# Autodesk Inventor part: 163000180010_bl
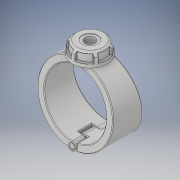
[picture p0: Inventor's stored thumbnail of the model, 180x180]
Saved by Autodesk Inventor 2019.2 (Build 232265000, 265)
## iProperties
Created: 2022-02
Part Number: 163000180010_bl
Material: Generic
Description: Plassadle Threaded 180x1''
Document SubType Name: Modeling
Designer: comp2
Density: 1 g/cm^3
Appearance: Default
Author: comp2
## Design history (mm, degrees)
derived "16300.ipt"
feature "Solid1::16300.ipt" dims "ScaleForDerivedMember" = 10
feature "Solid2::16300.ipt" dims "ScaleForDerivedMember" = 10
feature "Solid3::16300.ipt" dims "ScaleForDerivedMember" = 10
feature "Solid4::16300.ipt" dims "ScaleForDerivedMember" = 10
tag "TaggingFeature1"
body "Solid1"
body "Solid2"
body "Solid3"
body "Solid4"
other parameters: "d1" = 25 [user parameter], "E_" = 54 [user parameter], "E1" = 102 [user parameter], "H1" = 255 [user parameter], "H2" = 49 [user parameter], "H3" = 78 [user parameter], "H_costum" = 49 [user parameter], "Rp" = 30.291 [user parameter], "d128" = 36.1 [user parameter], "d7" = 209 [user parameter], "d8" = 85 deg [user parameter], "d9" = 45 deg [user parameter], "d10" = 102 [user parameter], "d11" = 49 [user parameter], "d12" = 25.27 [user parameter], "d13" = 42.84 [user parameter], "d14" = 45.4365 [user parameter], "d42" = 4 [user parameter], "d49" = 4.4 [user parameter], "d51" = 0 [user parameter], "d52" = 28 [user parameter], "d53" = 121 [user parameter], "d54" = 38.5 [user parameter], "d55" = 0 [user parameter], "d56" = 22 [user parameter], "d57" = 22 [user parameter], "d59" = 0 [user parameter], "d61" = 0 [user parameter], "d62" = 38.5 [user parameter], "d63" = 0 [user parameter], "d65" = 0 [user parameter], "d67" = 0 [user parameter], "d69" = 0 [user parameter], "d70" = 1 [user parameter], "d71" = 105.6 [user parameter], "d72" = 0 [user parameter], "d73" = 2 [user parameter], "d78" = 86.7 [user parameter], "d79" = 5.1 [user parameter], "d80" = 60 deg [user parameter], "d81" = 5.1 [user parameter], "d84" = 0 [user parameter], "d85" = 1 [user parameter], "d87" = 360 deg [user parameter], "d122" = 49 [user parameter], "d124" = 42.80128 [user parameter], "d125" = 1.805 [user parameter], "d127" = 255 [user parameter], "d129" = 30.291 [user parameter], "d130" = 25.74735 [user parameter], "d131" = 31.85 [user parameter], "d132" = 45 deg [user parameter], "d133" = 22.295 [user parameter], "d134" = 15.1455 [user parameter], "d136" = 0 [user parameter], "d138" = 0 [user parameter]
